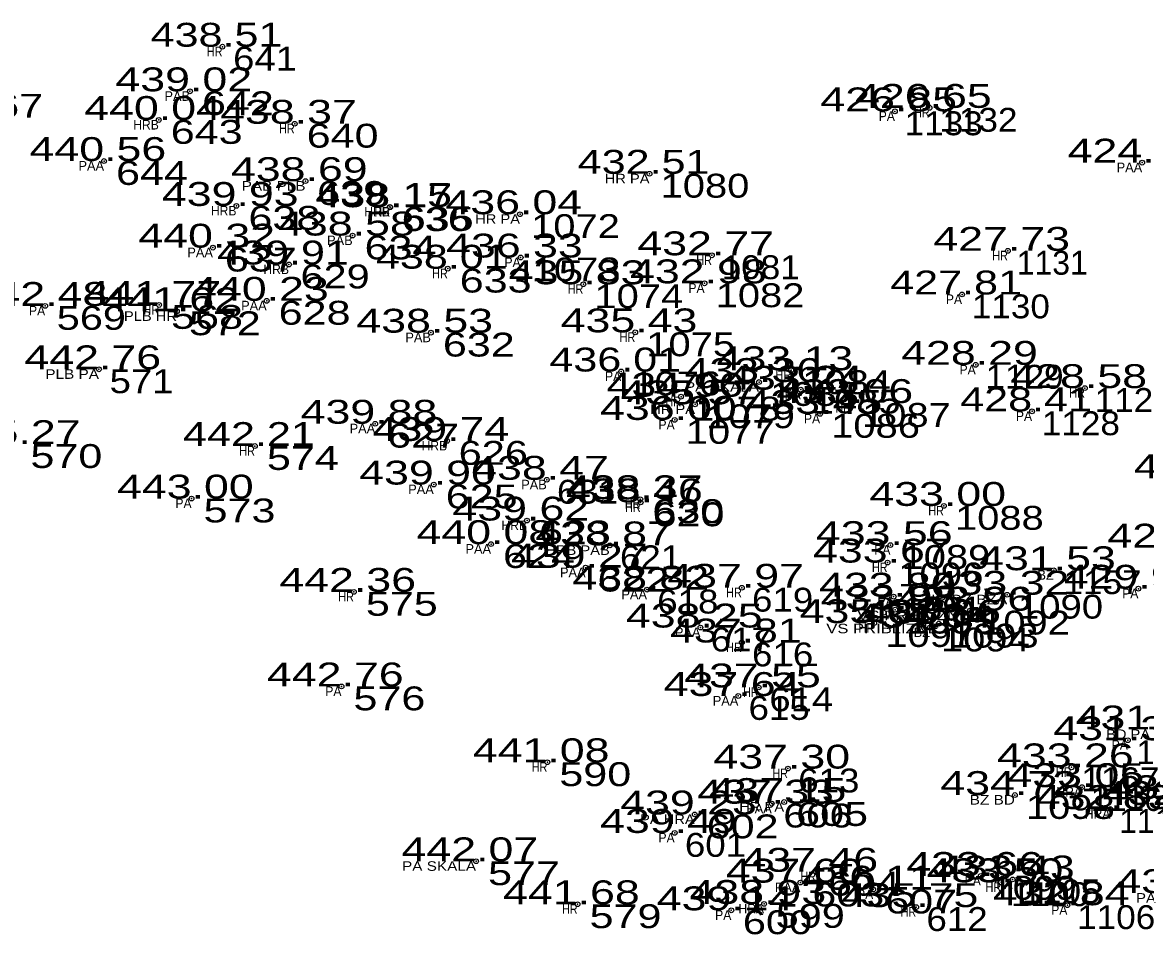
# Model space of a CAD drawing. Extents: x -639390 to -639074, y -1138747 to -1138358.
# Drawn here: x -639129.77 to -639094.48, y -1138725.69 to -1138697.05 of the extents above; entities that cross this region are included whole.
import ezdxf
from ezdxf.enums import TextEntityAlignment as Align

# ---------------------------------------------------------------- set-up
doc = ezdxf.new("R2010")
doc.units = 0
doc.header["$LTSCALE"] = 0.3
doc.header["$PDMODE"] = 32
doc.header["$PDSIZE"] = 0.15
for name, color, linetype in [('11', 7, 'Continuous'), ('12', 7, 'Continuous'), ('13', 7, 'Continuous'), ('57', 7, 'Continuous')]:
    doc.layers.add(name, color=color, linetype=linetype)

msp = doc.modelspace()

# ---------------------------------------------------------------- linework, layer by layer
at = {"layer": '11'}
for p in [(-639123.49, -1138697.81), (-639124.51, -1138699.21), (-639102.36, -1138699.84), (-639101.27, -1138699.73), (-639125.49, -1138700.11), (-639121.22, -1138700.23), (-639127.21, -1138701.4), (-639094.59, -1138701.45), (-639120.88, -1138702.03), (-639110.07, -1138701.8), (-639123.05, -1138702.81), (-639118.23, -1138702.84), (-639118.22, -1138702.85), (-639114.14, -1138703.07), (-639119.4, -1138703.74), (-639123.79, -1138704.12), (-639098.81, -1138704.22), (-639114.12, -1138704.43), (-639108.11, -1138704.36), (-639121.4, -1138704.65), (-639116.41, -1138704.78), (-639112.15, -1138705.27), (-639108.34, -1138705.24), (-639100.25, -1138705.59), (-639129.06, -1138705.95), (-639125.48, -1138705.92), (-639122.1, -1138705.79), (-639124.92, -1138706.12), (-639116.94, -1138706.79), (-639110.52, -1138706.78), (-639127.37, -1138707.94), (-639110.96, -1138708.01), (-639105.62, -1138707.97), (-639099.82, -1138707.8), (-639106.63, -1138708.34), (-639109.08, -1138708.8), (-639105.32, -1138708.58), (-639096.39, -1138708.53), (-639108.64, -1138709.04), (-639103.74, -1138709), (-639109.28, -1138709.53), (-639104.71, -1138709.34), (-639098.05, -1138709.26), (-639118.69, -1138709.65), (-639116.43, -1138710.19), (-639122.47, -1138710.35), (-639116.85, -1138711.56), (-639113.3, -1138711.41), (-639124.46, -1138712), (-639110.36, -1138712.02), (-639110.35, -1138712.12), (-639100.82, -1138712.23), (-639113.92, -1138712.69), (-639115.05, -1138713.43), (-639111.32, -1138713.47), (-639102.5, -1138713.46), (-639102.59, -1138714.01), (-639112.08, -1138714.17), (-639097.37, -1138714.25), (-639107.17, -1138714.8), (-639119.36, -1138714.93), (-639110.15, -1138714.86), (-639102.4, -1138715.08), (-639098.83, -1138715.02), (-639094.71, -1138714.83), (-639102.35, -1138715.49), (-639100, -1138715.52), (-639108.47, -1138716.05), (-639103.01, -1138715.91), (-639101.26, -1138716.05), (-639100.98, -1138715.93), (-639107.17, -1138716.52), (-639119.75, -1138717.9), (-639106.64, -1138717.93), (-639107.28, -1138718.2), (-639095.04, -1138719.59), (-639113.28, -1138720.28), (-639096.81, -1138720.44), (-639105.72, -1138720.48), (-639096.48, -1138721.06), (-639105.84, -1138721.53), (-639098.59, -1138721.31), (-639106.23, -1138721.58), (-639095.59, -1138721.75), (-639108.65, -1138721.92), (-639109.28, -1138722.5), (-639115.52, -1138723.39), (-639104.84, -1138723.72), (-639099.66, -1138723.85), (-639098.66, -1138723.96), (-639105.33, -1138724.06), (-639103.04, -1138724.28), (-639099.02, -1138724.05), (-639112.33, -1138724.74), (-639107.5, -1138724.93), (-639106.47, -1138724.73), (-639101.69, -1138724.83), (-639096.94, -1138724.77)]:
    msp.add_point(p, dxfattribs=at)

# ---------------------------------------------------------------- texts
at = {"layer": '12'}
for s, width, p in [('438.51 ', 1.35, (-639123.489, -1138697.81)), ('439.02 ', 1.4, (-639124.51, -1138699.21)), ('426.85 ', 1.4, (-639102.36, -1138699.84)), ('426.65 ', 1.4, (-639101.27, -1138699.73)), ('440.04 ', 1.4, (-639125.49, -1138700.11)), ('438.37 ', 1.4, (-639121.22, -1138700.23)), ('440.56 ', 1.4, (-639127.209, -1138701.4)), ('424.17 ', 1.4, (-639094.59, -1138701.45)), ('438.69 ', 1.4, (-639120.88, -1138702.03)), ('432.51 ', 1.35, (-639110.069, -1138701.8)), ('439.93 ', 1.4, (-639123.05, -1138702.81)), ('438.15 ', 1.4, (-639118.23, -1138702.84)), ('438.17 ', 1.4, (-639118.22, -1138702.85)), ('436.04 ', 1.4, (-639114.14, -1138703.07)), ('438.58 ', 1.4, (-639119.4, -1138703.74)), ('440.32 ', 1.4, (-639123.79, -1138704.12)), ('427.73 ', 1.4, (-639098.81, -1138704.22)), ('436.33 ', 1.4, (-639114.12, -1138704.43)), ('432.77 ', 1.4, (-639108.11, -1138704.36)), ('439.91 ', 1.35, (-639121.399, -1138704.65)), ('438.01 ', 1.35, (-639116.409, -1138704.78)), ('435.83 ', 1.4, (-639112.15, -1138705.27)), ('432.98 ', 1.4, (-639108.34, -1138705.24)), ('427.81 ', 1.35, (-639100.249, -1138705.59)), ('442.48 ', 1.4, (-639129.06, -1138705.95)), ('441.77 ', 1.4, (-639125.48, -1138705.92)), ('440.23 ', 1.4, (-639122.1, -1138705.79)), ('441.62 ', 1.4, (-639124.92, -1138706.12)), ('438.53 ', 1.4, (-639116.94, -1138706.79)), ('435.43 ', 1.4, (-639110.52, -1138706.78)), ('442.76 ', 1.4, (-639127.369, -1138707.94)), ('436.01 ', 1.35, (-639110.959, -1138708.01)), ('433.13 ', 1.4, (-639105.62, -1138707.97)), ('428.29 ', 1.4, (-639099.82, -1138707.8)), ('433.36 ', 1.4, (-639106.629, -1138708.34)), ('434.96 ', 1.4, (-639109.079, -1138708.8)), ('433.24 ', 1.4, (-639105.32, -1138708.58)), ('428.58 ', 1.4, (-639096.39, -1138708.53)), ('435.57 ', 1.4, (-639108.64, -1138709.04)), ('433.06 ', 1.4, (-639103.739, -1138709)), ('433.45 ', 1.4, (-639104.71, -1138709.34)), ('428.41 ', 1.35, (-639098.049, -1138709.26)), ('439.88 ', 1.4, (-639118.69, -1138709.65)), ('436.00 ', 1.4, (-639109.28, -1138709.53)), ('439.74 ', 1.4, (-639116.43, -1138710.19)), ('445.27 ', 1.4, (-639129.9, -1138710.29)), ('442.21 ', 1.35, (-639122.469, -1138710.35)), ('439.90 ', 1.4, (-639116.85, -1138711.56)), ('438.47 ', 1.4, (-639113.3, -1138711.41)), ('427.94 ', 1.4, (-639092.51, -1138711.36)), ('443.00 ', 1.4, (-639124.46, -1138712)), ('438.37 ', 1.4, (-639110.36, -1138712.02)), ('438.46 ', 1.4, (-639110.349, -1138712.12)), ('433.00 ', 1.4, (-639100.82, -1138712.23)), ('439.62 ', 1.4, (-639113.92, -1138712.69)), ('440.08 ', 1.4, (-639115.05, -1138713.43)), ('438.87 ', 1.4, (-639111.32, -1138713.47)), ('433.56 ', 1.4, (-639102.499, -1138713.46)), ('429.50 ', 1.4, (-639093.34, -1138713.54)), ('433.67 ', 1.4, (-639102.59, -1138714.01)), ('439.27 ', 1.4, (-639112.08, -1138714.17)), ('431.53 ', 1.4, (-639097.37, -1138714.25)), ('437.97 ', 1.4, (-639107.17, -1138714.8)), ('442.36 ', 1.4, (-639119.359, -1138714.93)), ('438.82 ', 1.4, (-639110.15, -1138714.86)), ('433.80 ', 1.4, (-639102.4, -1138715.08)), ('433.32 ', 1.4, (-639098.83, -1138715.02)), ('429.93 ', 1.4, (-639094.71, -1138714.83)), ('433.98 ', 1.4, (-639102.35, -1138715.49)), ('433.96 ', 1.4, (-639099.999, -1138715.52)), ('438.25 ', 1.4, (-639108.47, -1138716.05)), ('435.07 ', 1.4, (-639103.01, -1138715.91)), ('434.04 ', 1.4, (-639101.26, -1138716.05)), ('433.96 ', 1.4, (-639100.979, -1138715.93)), ('437.81 ', 1.35, (-639107.169, -1138716.52)), ('442.76 ', 1.4, (-639119.749, -1138717.9)), ('437.55 ', 1.4, (-639106.64, -1138717.93)), ('437.64 ', 1.4, (-639107.28, -1138718.2)), ('431.17 ', 1.4, (-639094.34, -1138719.25)), ('431.39 ', 1.4, (-639095.04, -1138719.59)), ('441.08 ', 1.4, (-639113.28, -1138720.28)), ('433.26 ', 1.4, (-639096.809, -1138720.44)), ('437.30 ', 1.4, (-639105.72, -1138720.48)), ('433.05 ', 1.4, (-639096.48, -1138721.06)), ('434.72 ', 1.4, (-639098.59, -1138721.31)), ('431.79 ', 1.4, (-639093.28, -1138721.44)), ('437.33 ', 1.4, (-639106.23, -1138721.58)), ('437.15 ', 1.4, (-639105.84, -1138721.53)), ('432.83 ', 1.4, (-639095.59, -1138721.75)), ('432.38 ', 1.4, (-639093.49, -1138721.62)), ('439.23 ', 1.4, (-639108.65, -1138721.92)), ('439.49 ', 1.4, (-639109.28, -1138722.5)), ('442.07 ', 1.4, (-639115.52, -1138723.39)), ('437.46 ', 1.4, (-639104.839, -1138723.72)), ('433.66 ', 1.4, (-639099.659, -1138723.85)), ('433.43 ', 1.4, (-639098.66, -1138723.96)), ('437.60 ', 1.4, (-639105.33, -1138724.06)), ('436.11 ', 1.35, (-639103.039, -1138724.28)), ('433.50 ', 1.4, (-639099.02, -1138724.05)), ('432.47 ', 1.4, (-639093.06, -1138724.39)), ('441.68 ', 1.4, (-639112.33, -1138724.74)), ('439.14 ', 1.4, (-639107.5, -1138724.93)), ('438.93 ', 1.4, (-639106.47, -1138724.73)), ('435.75 ', 1.4, (-639101.69, -1138724.83)), ('432.84 ', 1.4, (-639096.94, -1138724.77))]:
    msp.add_text(s, height=0.75, dxfattribs=dict(at, width=width)).set_placement(p, align=Align.CENTER)
at = {"layer": '13'}
for s, width, p in [(' 641', 1.2, (-639123.49, -1138698.56)), (' 642', 1.35, (-639124.51, -1138699.96)), (' 567', 1.35, (-639131.76, -1138700.04)), (' 1133', 1.1, (-639102.36, -1138700.59)), (' 1132', 1.1, (-639101.27, -1138700.48)), (' 643', 1.35, (-639125.49, -1138700.86)), (' 640', 1.35, (-639121.22, -1138700.98)), (' 644', 1.35, (-639127.21, -1138702.15)), (' 639', 1.3, (-639120.88, -1138702.78)), (' 1080', 1.25, (-639110.07, -1138702.55)), (' 638', 1.35, (-639123.05, -1138703.56)), (' 636', 1.3, (-639118.22, -1138703.6)), (' 635', 1.35, (-639118.23, -1138703.59)), (' 1072', 1.25, (-639114.14, -1138703.82)), (' 634', 1.35, (-639119.4, -1138704.49)), (' 637', 1.35, (-639123.79, -1138704.87)), (' 1073', 1.25, (-639114.12, -1138705.18)), (' 1081', 1.1, (-639108.11, -1138705.11)), (' 629', 1.3, (-639121.4, -1138705.4)), (' 633', 1.35, (-639116.41, -1138705.53)), (' 1074', 1.25, (-639112.15, -1138706.02)), (' 1082', 1.25, (-639108.34, -1138705.99)), (' 568', 1.35, (-639125.48, -1138706.67)), (' 628', 1.35, (-639122.1, -1138706.54)), (' 1130', 1.1, (-639100.25, -1138706.34)), (' 569', 1.3, (-639129.06, -1138706.7)), (' 572', 1.35, (-639124.92, -1138706.87)), (' 632', 1.35, (-639116.94, -1138707.54)), (' 1075', 1.25, (-639110.52, -1138707.53)), (' 571', 1.2, (-639127.37, -1138708.69)), (' 1076', 1.25, (-639110.96, -1138708.76)), (' 1084', 1.25, (-639105.62, -1138708.72)), (' 1129', 1.1, (-639099.82, -1138708.55)), (' 1083', 1.25, (-639106.63, -1138709.09)), (' 1085', 1.25, (-639105.32, -1138709.33)), (' 1127', 1.1, (-639096.39, -1138709.28)), (' 1078', 1.25, (-639109.08, -1138709.55)), (' 1079', 1.25, (-639108.64, -1138709.79)), (' 1087', 1.25, (-639103.74, -1138709.75)), (' 1086', 1.25, (-639104.71, -1138710.09)), (' 1128', 1.1, (-639098.05, -1138710.01)), (' 627', 1.35, (-639118.69, -1138710.4)), (' 1077', 1.25, (-639109.28, -1138710.28)), (' 570', 1.35, (-639129.9, -1138711.04)), (' 574', 1.35, (-639122.47, -1138711.1)), (' 626', 1.3, (-639116.43, -1138710.94)), (' 625', 1.35, (-639116.85, -1138712.31)), (' 631', 1.15, (-639113.3, -1138712.16)), (' 573', 1.35, (-639124.46, -1138712.75)), (' 630', 1.35, (-639110.36, -1138712.77)), (' 620', 1.35, (-639110.35, -1138712.87)), (' 1088', 1.25, (-639100.82, -1138712.98)), (' 623', 1.35, (-639113.92, -1138713.44)), (' 624', 1.35, (-639115.05, -1138714.18)), (' 621', 1.15, (-639111.32, -1138714.22)), (' 1089', 1.25, (-639102.5, -1138714.21)), (' 1096', 1.2, (-639102.59, -1138714.76)), (' 622', 1.35, (-639112.08, -1138714.92)), (' 1157', 1.1, (-639097.37, -1138715)), (' 575', 1.35, (-639119.36, -1138715.68)), (' 618', 1.15, (-639110.15, -1138715.61)), (' 619', 1.15, (-639107.17, -1138715.55)), (' 1091', 1.1, (-639102.4, -1138715.83)), (' 1090', 1.2, (-639098.83, -1138715.77)), (' 1095', 1.25, (-639102.35, -1138716.24)), (' 1092', 1.25, (-639100, -1138716.27)), (' 617', 1.15, (-639108.47, -1138716.8)), (' 1097', 1.25, (-639103.01, -1138716.66)), (' 1094', 1.25, (-639101.26, -1138716.8)), (' 1093', 1.25, (-639100.98, -1138716.68)), (' 616', 1.15, (-639107.17, -1138717.27)), (' 576', 1.35, (-639119.75, -1138718.65)), (' 614', 1.2, (-639106.64, -1138718.68)), (' 615', 1.15, (-639107.28, -1138718.95)), (' 590', 1.35, (-639113.28, -1138721.03)), (' 613', 1.15, (-639105.72, -1138721.23)), (' 1167', 1.1, (-639096.81, -1138721.19)), (' 1098', 1.25, (-639098.59, -1138722.06)), (' 606', 1.3, (-639106.23, -1138722.33)), (' 605', 1.35, (-639105.84, -1138722.28)), (' 602', 1.35, (-639108.65, -1138722.67)), (' 601', 1.15, (-639109.28, -1138723.25)), (' 577', 1.35, (-639115.52, -1138724.14)), (' 604', 1.35, (-639104.84, -1138724.47)), (' 1099', 1.2, (-639099.66, -1138724.6)), (' 603', 1.35, (-639105.33, -1138724.81)), (' 607', 1.35, (-639103.04, -1138725.03)), (' 1100', 1.1, (-639099.02, -1138724.8)), (' 1105', 1.1, (-639098.66, -1138724.71)), (' 579', 1.35, (-639112.33, -1138725.49)), (' 600', 1.3, (-639107.5, -1138725.68)), (' 599', 1.3, (-639106.47, -1138725.48)), (' 612', 1.15, (-639101.69, -1138725.58)), (' 1106', 1.1, (-639096.94, -1138725.52))]:
    msp.add_text(s, height=0.75, dxfattribs=dict(at, width=width)).set_placement(p)
for s, p in [(' 1131', (-639098.81, -1138704.97)), (' 1117', (-639095.04, -1138720.34)), (' 1116', (-639096.48, -1138721.81)), (' 1115', (-639095.59, -1138722.5))]:
    msp.add_text(s, height=0.75, dxfattribs=at).set_placement(p)
at = {"layer": '57'}
for s, width, p in [('HR', 0.85, (-639123.489, -1138698.11)), ('PA', 0.95, (-639102.36, -1138700.14)), ('HR', 0.85, (-639101.269, -1138700.03)), ('HRB', 0.95, (-639125.489, -1138700.41)), ('HR', 0.85, (-639121.219, -1138700.53)), ('PAB PLB', 1.2, (-639120.879, -1138702.33)), ('HR PA', 1.15, (-639110.07, -1138702.1)), ('HRB', 0.95, (-639123.049, -1138703.11)), ('HRB', 0.95, (-639118.229, -1138703.14)), ('HR', 0.85, (-639118.219, -1138703.15)), ('HR PA', 1.15, (-639114.14, -1138703.37)), ('PA', 0.95, (-639114.12, -1138704.73)), ('HR', 0.85, (-639108.109, -1138704.66)), ('HR', 0.85, (-639098.809, -1138704.52)), ('HRB', 0.95, (-639121.399, -1138704.95)), ('HR', 0.85, (-639116.409, -1138705.08)), ('HR', 0.85, (-639112.149, -1138705.57)), ('PA', 0.95, (-639108.34, -1138705.54)), ('HR', 0.85, (-639125.479, -1138706.22)), ('PA', 0.95, (-639100.25, -1138705.89)), ('PA', 0.95, (-639129.06, -1138706.25)), ('PLB HR', 1.15, (-639124.919, -1138706.42)), ('HR', 0.85, (-639110.519, -1138707.08)), ('PLB PA', 1.2, (-639127.37, -1138708.24)), ('PA', 0.95, (-639110.96, -1138708.31)), ('HR', 0.85, (-639105.619, -1138708.27)), ('PA', 0.95, (-639099.82, -1138708.1)), ('PA SKALA', 1.2, (-639106.63, -1138708.64)), ('PA', 0.95, (-639105.32, -1138708.88)), ('HR', 0.85, (-639096.389, -1138708.83)), ('HR PA', 1.15, (-639108.64, -1138709.34)), ('HR', 0.85, (-639109.079, -1138709.1)), ('HR', 0.85, (-639103.739, -1138709.3)), ('PA', 0.95, (-639104.71, -1138709.64)), ('PA', 0.95, (-639098.05, -1138709.56)), ('PA', 0.95, (-639109.28, -1138709.83)), ('HR', 0.85, (-639122.469, -1138710.65)), ('HRB', 0.95, (-639116.429, -1138710.49)), ('PA', 0.95, (-639124.46, -1138712.3)), ('HR', 0.85, (-639110.359, -1138712.32)), ('HR', 0.85, (-639110.349, -1138712.42)), ('HR', 0.85, (-639100.819, -1138712.53)), ('HRB', 0.95, (-639113.919, -1138712.99)), ('HRB PAB', 1.15, (-639111.319, -1138713.77)), ('PA', 0.95, (-639102.5, -1138713.76)), ('HR', 0.85, (-639102.589, -1138714.31)), ('HR', 0.85, (-639119.359, -1138715.23)), ('HR', 0.85, (-639107.169, -1138715.1)), ('PA', 0.95, (-639102.4, -1138715.38)), ('HR BZ BZA', 1.25, (-639098.83, -1138715.32)), ('PA', 0.95, (-639094.71, -1138715.13)), ('VS PRIBLIZNE', 1.3, (-639100, -1138715.82)), ('PA', 0.95, (-639102.35, -1138715.79)), ('VS PRIBLIZNE', 1.3, (-639100.98, -1138716.23)), ('HR', 0.85, (-639103.009, -1138716.21)), ('HR', 0.85, (-639107.169, -1138716.82)), ('PA', 0.95, (-639119.75, -1138718.2)), ('HR', 0.85, (-639106.639, -1138718.23)), ('BD PA', 1.15, (-639094.34, -1138719.55)), ('PA', 0.95, (-639095.04, -1138719.89)), ('HR', 0.85, (-639113.279, -1138720.58)), ('HR', 0.85, (-639105.719, -1138720.78)), ('HR', 0.85, (-639096.809, -1138720.74)), ('HRA', 0.95, (-639096.48, -1138721.36)), ('BZ BD', 1.2, (-639098.59, -1138721.61)), ('HR PA', 1.15, (-639105.84, -1138721.83)), ('HRA', 0.95, (-639095.59, -1138722.05)), ('PA HRA', 1.15, (-639108.65, -1138722.22)), ('PA', 0.95, (-639109.28, -1138722.8)), ('PA SKALA', 1.2, (-639115.52, -1138723.69)), ('HR', 0.85, (-639104.839, -1138724.02)), ('PA', 0.95, (-639099.66, -1138724.15)), ('PA', 0.95, (-639103.04, -1138724.58)), ('HR', 0.85, (-639099.019, -1138724.35)), ('PA', 0.95, (-639098.66, -1138724.26)), ('PA HRA', 1.15, (-639093.06, -1138724.69)), ('HR', 0.85, (-639112.329, -1138725.04)), ('PA', 0.95, (-639107.5, -1138725.23)), ('HRA', 0.95, (-639106.47, -1138725.03)), ('HR', 0.85, (-639101.689, -1138725.13)), ('PA', 0.95, (-639096.94, -1138725.07))]:
    msp.add_text(s, height=0.3, dxfattribs=dict(at, width=width)).set_placement(p, align=Align.RIGHT)
for s, p in [('PAB', (-639124.509, -1138699.51)), ('PAA', (-639127.21, -1138701.7)), ('PAA', (-639094.59, -1138701.75)), ('PAB', (-639119.399, -1138704.04)), ('PAA', (-639123.79, -1138704.42)), ('PAA', (-639122.1, -1138706.09)), ('PAB', (-639116.939, -1138707.09)), ('PAA', (-639118.69, -1138709.95)), ('PAA', (-639116.85, -1138711.86)), ('PAB', (-639113.299, -1138711.71)), ('PAA', (-639115.05, -1138713.73)), ('PAA', (-639112.08, -1138714.47)), ('BZ', (-639097.369, -1138714.55)), ('PAA', (-639110.15, -1138715.16)), ('PAA', (-639108.47, -1138716.35)), ('BZ', (-639101.259, -1138716.35)), ('PAA', (-639107.28, -1138718.5)), ('PAA', (-639106.23, -1138721.88)), ('PAA', (-639105.33, -1138724.36))]:
    msp.add_text(s, height=0.3, dxfattribs=at).set_placement(p, align=Align.RIGHT)

doc.saveas('drawing.dxf')
